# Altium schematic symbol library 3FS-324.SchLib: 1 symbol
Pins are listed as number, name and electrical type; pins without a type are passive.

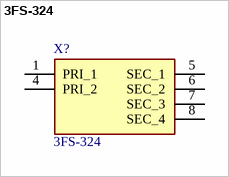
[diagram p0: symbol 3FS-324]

## 3FS-324
designator X?
Power Transformers POWER TRANSFORMER; Manufacturer_Name: Tamura; Geometry.Height: 32.1mm
footprint 3FS324
pins: 1 PRI_1, 4 PRI_2, 5 SEC_1, 6 SEC_2, 7 SEC_3, 8 SEC_4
